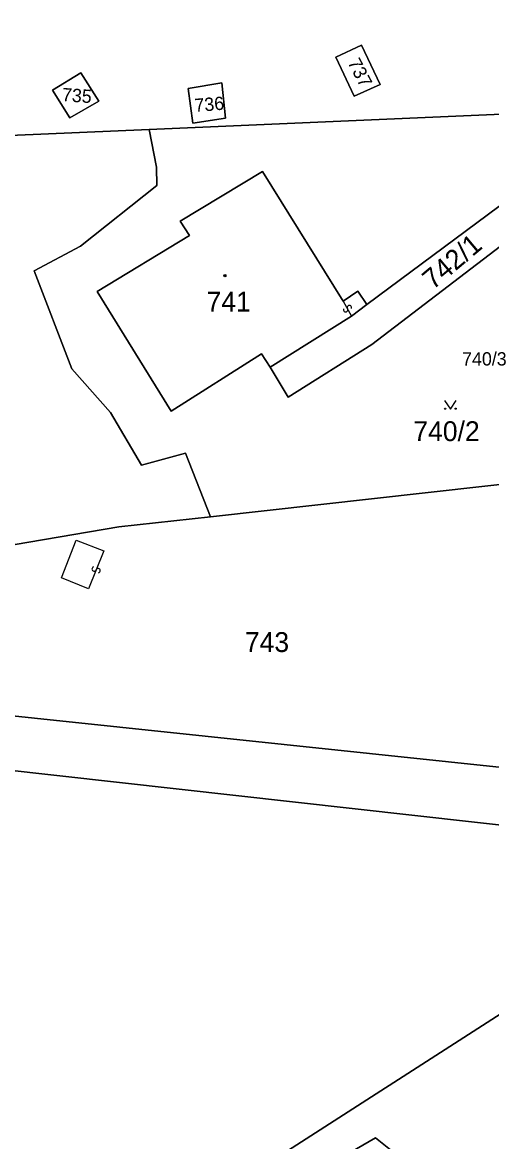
# Model space of a CAD drawing. Extents: x -600309 to -598967, y -1161267 to -1160292.
# Drawn here: x -599532.9 to -599492.6, y -1160977.1 to -1160881.2 of the extents above; entities that cross this region are included whole.
import ezdxf

# ---------------------------------------------------------------- set-up
doc = ezdxf.new("R2010")
doc.units = 0
for name, color, linetype in [('Level 1', 7, 'Continuous'), ('Level 13', 7, 'Continuous'), ('Level 3', 7, 'Continuous'), ('Level 4', 7, 'Continuous'), ('Level 5', 7, 'Continuous'), ('Level 57', 7, 'Continuous'), ('Level 60', 7, 'Continuous')]:
    doc.layers.add(name, color=color, linetype=linetype)

msp = doc.modelspace()

# ---------------------------------------------------------------- linework, layer by layer
at = {"layer": 'Level 1'}
for points in [[(-599505.99, -1160884.18), (-599503.77, -1160883.17), (-599502.19, -1160886.54), (-599504.4, -1160887.52), (-599505.99, -1160884.18)], [(-599530.28, -1160887.02), (-599527.84, -1160885.54), (-599526.31, -1160887.96), (-599528.79, -1160889.4), (-599530.28, -1160887.02)], [(-599518.64, -1160886.88), (-599515.77, -1160886.4), (-599515.43, -1160889.43), (-599518.23, -1160889.84), (-599518.64, -1160886.88)], [(-599521.99, -1160890.39), (-599488.46, -1160888.93)], [(-599479.07, -1160888.79), (-599491.99, -1160897), (-599503.33, -1160905.39)], [(-599521.99, -1160890.39), (-599539.93, -1160891.17), (-599547.45, -1160892.09)], [(-599521.99, -1160890.39), (-599521.35, -1160893.62), (-599521.33, -1160895.2), (-599527.88, -1160900.38), (-599531.85, -1160902.49), (-599528.61, -1160910.91), (-599525.31, -1160914.64), (-599522.65, -1160919.14), (-599518.88, -1160918.13), (-599516.72, -1160923.57)], [(-599505.34, -1160905.09), (-599512.26, -1160893.99), (-599519.34, -1160898.24), (-599518.54, -1160899.48), (-599526.44, -1160904.28), (-599520.11, -1160914.53), (-599512.35, -1160909.61), (-599511.62, -1160910.76)], [(-599511.62, -1160910.76), (-599510.08, -1160913.32), (-599502.9, -1160908.81), (-599491.85, -1160900.39)], [(-599503.33, -1160905.39), (-599504.08, -1160904.25), (-599505.34, -1160905.09)], [(-599503.33, -1160905.39), (-599504.63, -1160906.39)], [(-599504.63, -1160906.39), (-599511.62, -1160910.76)], [(-599516.72, -1160923.57), (-599479.39, -1160919.42)], [(-599516.72, -1160923.57), (-599524.58, -1160924.44), (-599561.87, -1160930.78)], [(-599560.03, -1160937.87), (-599489, -1160945.35), (-599487.6, -1160945.48)], [(-599560.13, -1160942.37), (-599489.23, -1160950.29)], [(-599488.59, -1160964.84), (-599490.61, -1160965.36), (-599512.52, -1160979.46)], [(-599501.29, -1160977.83), (-599502.57, -1160976.78), (-599511.13, -1160981.73), (-599516.34, -1160990.29), (-599525.08, -1161006.39), (-599531.89, -1161023.78), (-599530.59, -1161022.45)]]:
    msp.add_lwpolyline(points, dxfattribs=at)
at = {"layer": 'Level 13'}
for centre, start, end in [((-599505.142, -1160905.828), 155.79961, 28.38961), ((-599504.817, -1160905.653), 336.01406, 208.11206), ((-599526.71, -1160928.05), 105.02533, 337.61533), ((-599526.37, -1160928.191), 285.23979, 157.33779)]:
    msp.add_arc(centre, 0.184, start, end, dxfattribs=at)
at = {"layer": 'Level 3'}
for points in [[(-599505.34, -1160905.09), (-599504.63, -1160906.39)], [(-599528.24, -1160925.57), (-599525.87, -1160926.49), (-599527.2, -1160929.76), (-599529.5, -1160928.8), (-599528.24, -1160925.57)]]:
    msp.add_lwpolyline(points, dxfattribs=at)
at = {"layer": 'Level 5'}
msp.add_lwpolyline([(-599496.651, -1160913.61), (-599496.15, -1160914.36), (-599495.65, -1160913.61)], dxfattribs=at)
for centre, radius in [((-599515.49, -1160902.91), 0.09), ((-599515.49, -1160902.91), 0.0521), ((-599496.6, -1160914.31), 0.05), ((-599495.701, -1160914.31), 0.05)]:
    msp.add_circle(centre, radius, dxfattribs=at)
at = {"layer": 'Level 60'}
for points in [[(-599485.56, -1160874.64), (-599479.62, -1160886.55), (-599478.75, -1160888.22), (-599488.46, -1160888.93), (-599521.99, -1160890.39), (-599539.93, -1160891.17), (-599547.45, -1160892.09), (-599545.11, -1160890.17), (-599548.78, -1160886.13), (-599551.17, -1160888.12), (-599547.45, -1160892.09), (-599579.23, -1160895.89), (-599610.7, -1160901.38), (-599623.88, -1160902.01), (-599627.26, -1160901.81), (-599623.8, -1160900.4), (-599625.9, -1160895.19), (-599629.23, -1160896.54), (-599627.26, -1160901.81), (-599628.39, -1160901.69), (-599634.95, -1160898.11), (-599638.48, -1160895.36), (-599648.13, -1160877.1)], [(-599479.39, -1160919.42), (-599516.72, -1160923.57), (-599518.88, -1160918.13), (-599522.65, -1160919.14), (-599525.31, -1160914.64), (-599528.61, -1160910.91), (-599531.85, -1160902.49), (-599527.88, -1160900.38), (-599521.33, -1160895.2), (-599521.35, -1160893.62), (-599521.99, -1160890.39), (-599488.46, -1160888.93)], [(-599491.99, -1160897), (-599503.33, -1160905.39), (-599504.08, -1160904.25), (-599505.34, -1160905.09), (-599512.26, -1160893.99), (-599519.34, -1160898.24), (-599518.54, -1160899.48), (-599526.44, -1160904.28), (-599520.11, -1160914.53), (-599512.35, -1160909.61), (-599511.62, -1160910.76), (-599510.08, -1160913.32), (-599502.9, -1160908.81), (-599491.85, -1160900.39)], [(-599610.7, -1160901.38), (-599579.23, -1160895.89), (-599570.78, -1160924.47), (-599569.11, -1160929.21), (-599568.09, -1160931.83), (-599566.1, -1160937.3), (-599560.45, -1160937.81), (-599560.03, -1160937.87), (-599489, -1160945.35), (-599487.6, -1160945.48), (-599486.18, -1160950.38), (-599489.23, -1160950.29), (-599560.13, -1160942.37), (-599560.56, -1160942.31), (-599566.95, -1160941.53), (-599576.62, -1160937.63), (-599576.9, -1160937.73), (-599578.2, -1160933.98), (-599578.94, -1160929.75), (-599582.1, -1160908.78), (-599584.9, -1160905.11), (-599590.9, -1160903.6)], [(-599630.1, -1160977.09), (-599570.78, -1160962.58), (-599570.9, -1160962.27), (-599568.04, -1160961.36), (-599567.91, -1160961.97), (-599562.84, -1160960.63), (-599565.04, -1160950.54), (-599562.75, -1160950.25), (-599563.61, -1160944.23), (-599566.3, -1160944.61), (-599566.95, -1160941.53), (-599560.56, -1160942.31), (-599560.13, -1160942.37), (-599489.23, -1160950.29), (-599486.18, -1160950.38), (-599482.56, -1160962.83), (-599483.73, -1160963.17), (-599483.91, -1160963.63), (-599488.59, -1160964.84), (-599490.61, -1160965.36), (-599512.52, -1160979.46), (-599599.9, -1161001.22)], [(-599512.52, -1160979.46), (-599490.61, -1160965.36), (-599488.59, -1160964.84), (-599483.91, -1160963.63), (-599491.05, -1160981.38)], [(-599511.13, -1160981.73), (-599502.57, -1160976.78), (-599501.29, -1160977.83)], [(-599501.29, -1160977.83), (-599502.57, -1160976.78), (-599511.13, -1160981.73)]]:
    msp.add_lwpolyline(points, dxfattribs=at)
for points in [[(-599503.77, -1160883.17), (-599505.99, -1160884.18), (-599504.4, -1160887.52), (-599502.19, -1160886.54)], [(-599505.99, -1160884.18), (-599503.77, -1160883.17), (-599502.19, -1160886.54), (-599504.4, -1160887.52)], [(-599527.84, -1160885.54), (-599530.28, -1160887.02), (-599528.79, -1160889.4), (-599526.31, -1160887.96)], [(-599530.28, -1160887.02), (-599527.84, -1160885.54), (-599526.31, -1160887.96), (-599528.79, -1160889.4)], [(-599515.77, -1160886.4), (-599518.64, -1160886.88), (-599518.23, -1160889.84), (-599515.43, -1160889.43)], [(-599518.64, -1160886.88), (-599515.77, -1160886.4), (-599515.43, -1160889.43), (-599518.23, -1160889.84)], [(-599504.63, -1160906.39), (-599503.33, -1160905.39), (-599491.99, -1160897), (-599479.07, -1160888.79), (-599478.75, -1160888.22), (-599476.69, -1160891.89), (-599477.1, -1160892.12), (-599479.13, -1160893.28), (-599479.36, -1160892.88), (-599491.85, -1160900.39), (-599502.9, -1160908.81), (-599510.08, -1160913.32), (-599511.62, -1160910.76)], [(-599539.93, -1160891.17), (-599521.99, -1160890.39), (-599521.35, -1160893.62), (-599521.33, -1160895.2), (-599527.88, -1160900.38), (-599531.85, -1160902.49), (-599528.61, -1160910.91), (-599525.31, -1160914.64), (-599522.65, -1160919.14), (-599518.88, -1160918.13), (-599516.72, -1160923.57), (-599524.58, -1160924.44), (-599561.87, -1160930.78), (-599568.09, -1160931.83), (-599569.11, -1160929.21), (-599570.78, -1160924.47), (-599579.23, -1160895.89), (-599547.45, -1160892.09)], [(-599503.33, -1160905.39), (-599504.63, -1160906.39), (-599511.62, -1160910.76), (-599512.35, -1160909.61), (-599520.11, -1160914.53), (-599526.44, -1160904.28), (-599518.54, -1160899.48), (-599519.34, -1160898.24), (-599512.26, -1160893.99), (-599505.34, -1160905.09), (-599504.08, -1160904.25)], [(-599566.1, -1160937.3), (-599568.09, -1160931.83), (-599561.87, -1160930.78), (-599524.58, -1160924.44), (-599516.72, -1160923.57), (-599479.39, -1160919.42), (-599479.09, -1160925.54), (-599483.59, -1160926.84), (-599481.91, -1160932.72), (-599482.75, -1160932.96), (-599482.33, -1160934.41), (-599481.37, -1160934.13), (-599480.29, -1160938.1), (-599480.15, -1160938.6), (-599488.87, -1160941.13), (-599487.6, -1160945.48), (-599489, -1160945.35), (-599560.03, -1160937.87), (-599560.45, -1160937.81)]]:
    msp.add_lwpolyline(points, close=True, dxfattribs=at)

# ---------------------------------------------------------------- texts
at = {"layer": 'Level 4'}
for s, height, rotation, p in [('737', 1.14, 297.45099, (-599504.992, -1160884.646)), ('735', 1.14, 355.91436, (-599529.492, -1160887.954)), ('736', 1.14, 4.85307, (-599518.053, -1160888.9)), ('742/1', 1.7, 40.05045, (-599497.656, -1160904.171))]:
    msp.add_text(s, height=height, rotation=rotation, dxfattribs=at).set_placement(p)
for s, p in [('741', (-599517.07, -1160905.99)), ('740/2', (-599499.332, -1160917.09)), ('743', (-599513.78, -1160935.16))]:
    msp.add_text(s, height=1.7, dxfattribs=at).set_placement(p)
at = {"layer": 'Level 57'}
msp.add_text('740/3', height=1.14, rotation=0.05166, dxfattribs=at).set_placement((-599495.145, -1160910.614))

doc.saveas('drawing.dxf')
